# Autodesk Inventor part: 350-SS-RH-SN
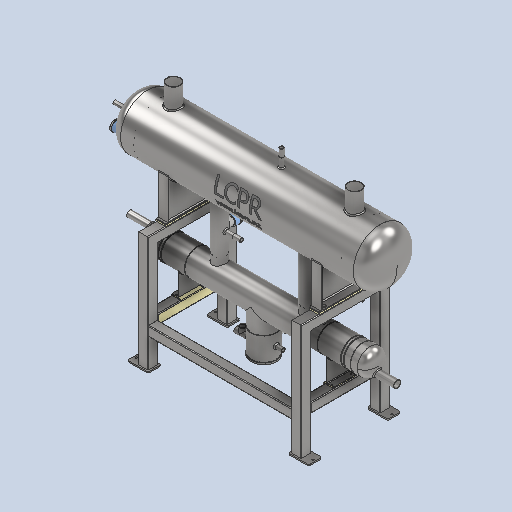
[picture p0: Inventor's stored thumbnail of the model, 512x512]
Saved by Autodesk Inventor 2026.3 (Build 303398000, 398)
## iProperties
Created: 2026-05
Part Number: 350-SS-RH-SN
Material: Generic
Document SubType Name: Modeling
Designer: rva
Density: 1 g/cm^3
Appearance: Default
Author: rva
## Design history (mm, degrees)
derived "350-SS-RH-SN.iam"
body "Solid1"
node "LPR-350-Frame Assembly.iam:1::LCPR-SS-350-135 x 85 Frame Foo"
node "LPR-350-Frame Assembly.iam:1::LCPR-SS-350-135 x 85 Frame Foo"
node "LPR-350-Frame Assembly.iam:1::LCPR-SS-350-135 x 85 Frame Foo"
node "LPR-350-Frame Assembly.iam:1::LCPR-SS-350-135 x 85 Frame Foo"
node "Sub-150-75-1171-30-40-32-SS-RH.iam:1::ISO 5251 Equal Tee DN1"
node "Sub-150-75-1171-30-40-32-SS-RH.iam:1::150-30-SS-Hole Sub Coo"
node "Sub-150-75-1171-30-40-32-SS-RH.iam:1::150-30-SS-Hole Sub Coo"
node "Sub-150-75-1171-30-40-32-SS-RH.iam:1::150 mm-SS- Subcooler L"
node "Sub-150-75-1171-30-40-32-SS-RH.iam:1::LCPR-150-SS-Blank Plat"
node "Sub-150-75-1171-30-40-32-SS-RH.iam:1::150 mm-SS- Subcooler L"
node "Sub-150-75-1171-30-40-32-SS-RH.iam:1::1-2 Inch NPT Socket - "
node "Sub-150-75-1171-30-40-32-SS-RH.iam:1::1-2 Inch NPT Socket - "
node "Sub-150-75-1171-30-40-32-SS-RH.iam:1::1-2 Inch NPT Socket - "
node "Sub-150-75-1171-30-40-32-SS-RH.iam:1::H1100-R.ipt:1"
node "Sub-150-75-1171-30-40-32-SS-RH.iam:1::H1100-R.ipt:2"
node "Sub-150-75-1171-30-40-32-SS-RH.iam:1::Welds"
node "Nylon Heat Tranfer Spacer 348x65.ipt:1"
node "Nylon Heat Tranfer Spacer 348x65.ipt:2"
node "AS 1111 - Metric M10 x 100:1"
node "AS 1112 (4) - Metric M10:1"
node "AS 1237 (4.1) 10 mm:1"
node "AS 1237 (4.1) 10 mm:2"
node "AS 1111 - Metric M10 x 100:2"
node "AS 1112 (4) - Metric M10:2"
node "AS 1237 (4.1) 10 mm:3"
node "AS 1237 (4.1) 10 mm:4"
node "AS 1111 - Metric M10 x 100:3"
node "AS 1112 (4) - Metric M10:3"
node "AS 1237 (4.1) 10 mm:5"
node "AS 1237 (4.1) 10 mm:6"
node "AS 1111 - Metric M10 x 100:4"
node "AS 1112 (4) - Metric M10:4"
node "AS 1237 (4.1) 10 mm:7"
node "AS 1237 (4.1) 10 mm:8"
node "350-SS-SHELL-SN-WELD.iam:1::LCPR-LOGO.ipt:1"
node "350-SS-SHELL-SN-WELD.iam:1::LCPR-SS-350-Leg Assembly.iam:1::"
node "350-SS-SHELL-SN-WELD.iam:1::LCPR-SS-350-Leg Assembly.iam:2::"
node "350-SS-SHELL-SN-WELD.iam:1::350 mm-SS- Dome End Cap.ipt:1"
node "350-SS-SHELL-SN-WELD.iam:1::350 mm-SS- Dome End Cap.ipt:2"
node "350-SS-SHELL-SN-WELD.iam:1::H1100-R.ipt:1"
node "350-SS-SHELL-SN-WELD.iam:1::Welds"
node "Nylon Heat Tranfer Spacer 145x65.ipt:1"
node "Nylon Heat Tranfer Spacer 145x65.ipt:2"
node "350-SS-RH-SN.iam_Bodies"
